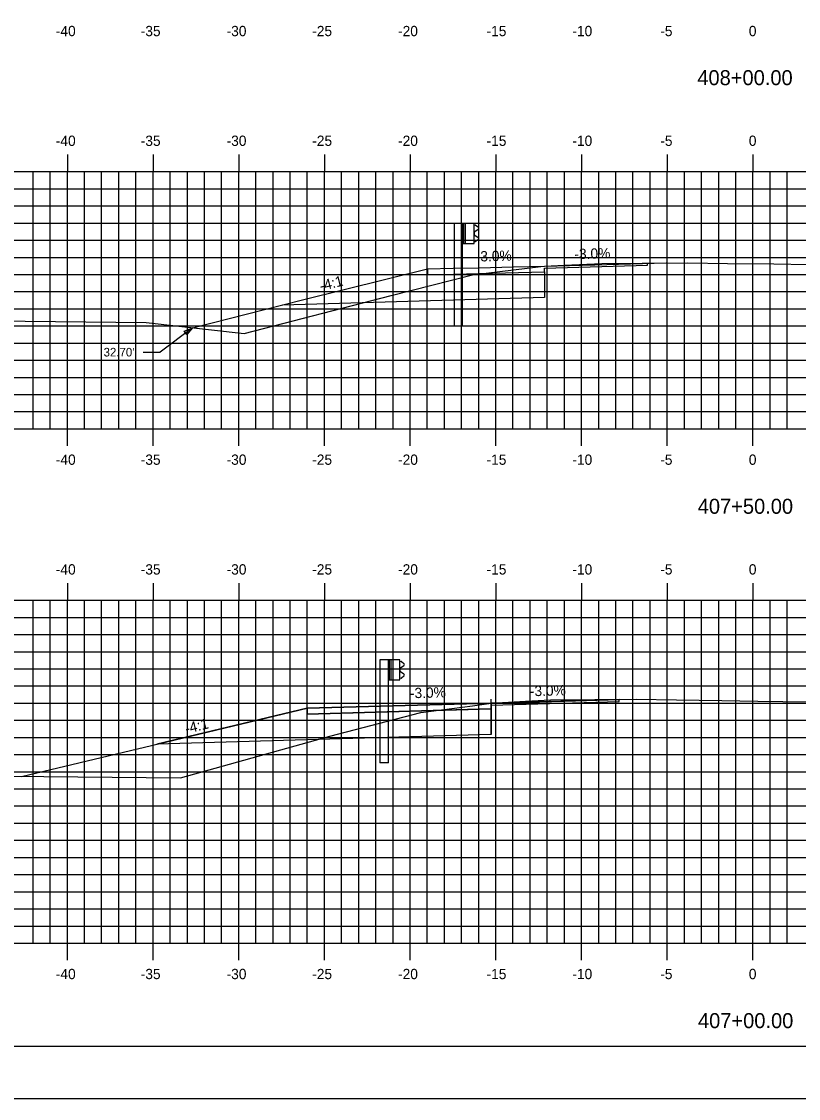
# Model space of a CAD drawing. Extents: x 1160718 to 1173142, y 616002 to 617630.
# Drawn here: x 1167258.6 to 1167304, y 616613.9 to 616676.7 of the extents above; entities that cross this region are included whole.
import ezdxf

# ---------------------------------------------------------------- set-up
doc = ezdxf.new("R2010")
doc.units = 0
for name, color, linetype in [('ANNOTATION', 7, 'Continuous'), ('BORDER', 7, 'Continuous'), ('D_Guardrail_Beam_Lt', 7, 'Continuous'), ('D_Roadway_Centerline', 7, 'Continuous'), ('D_Roadway_Edge_Shoulder', 7, 'Continuous'), ('D_Roadway_Edge_TW', 7, 'Continuous'), ('D_Roadway_SubGrade', 7, 'Continuous'), ('H_V ANNOTATION', 7, 'Continuous'), ('MAJOR', 7, 'Continuous'), ('MINOR', 7, 'Continuous'), ('PLOT BOUNDARY', 7, 'Continuous'), ('S_Roadway_Centerline', 7, 'Continuous'), ('SHADING', 7, 'Continuous')]:
    doc.layers.add(name, color=color, linetype=linetype)

msp = doc.modelspace()

# ---------------------------------------------------------------- linework, layer by layer
at = {"layer": 'ANNOTATION'}
for p, q in [((1167268.607, 616658.822), (1167266.736, 616657.397)), ((1167265.736, 616657.397), (1167266.736, 616657.397)), ((1167286.041, 616636.596), (1167286.041, 616635.096))]:
    msp.add_line(p, q, dxfattribs=at)
msp.add_lwpolyline([(1167268.133, 616658.618), (1167268.607, 616658.822), (1167268.285, 616658.419)], close=True, dxfattribs=at)
at = {"layer": 'BORDER'}
msp.add_line((1167226.316, 616616.928), (1167386.316, 616616.928), dxfattribs=at)
at = {"layer": 'D_Guardrail_Beam_Lt'}
for p, q in [((1167283.885, 616664.909), (1167283.885, 616658.909)), ((1167284.355, 616664.909), (1167283.885, 616664.909)), ((1167285.043, 616664.909), (1167284.355, 616664.909)), ((1167284.355, 616664.909), (1167284.355, 616663.742)), ((1167284.418, 616664.909), (1167284.418, 616663.742)), ((1167284.522, 616664.909), (1167284.522, 616663.742)), ((1167285.043, 616663.742), (1167285.043, 616664.909)), ((1167285.043, 616664.825), (1167285.117, 616664.811)), ((1167285.133, 616664.804), (1167285.276, 616664.704)), ((1167285.047, 616664.36), (1167285.047, 616664.29)), ((1167285.276, 616664.561), (1167285.081, 616664.425)), ((1167285.081, 616664.226), (1167285.276, 616664.09)), ((1167284.355, 616663.742), (1167285.043, 616663.742)), ((1167284.376, 616658.909), (1167284.376, 616663.742)), ((1167285.117, 616663.84), (1167285.043, 616663.825)), ((1167285.276, 616663.947), (1167285.133, 616663.847)), ((1167284.376, 616658.909), (1167283.885, 616658.909)), ((1167279.554, 616639.453), (1167279.554, 616633.453)), ((1167280.025, 616639.453), (1167279.554, 616639.453)), ((1167279.554, 616639.453), (1167279.554, 616633.453)), ((1167280.025, 616639.453), (1167279.554, 616639.453)), ((1167280.712, 616639.453), (1167280.025, 616639.453)), ((1167280.025, 616639.453), (1167280.025, 616638.286)), ((1167280.712, 616639.453), (1167280.025, 616639.453)), ((1167280.025, 616639.453), (1167280.025, 616638.286)), ((1167280.087, 616639.453), (1167280.087, 616638.286)), ((1167280.087, 616639.453), (1167280.087, 616638.286)), ((1167280.192, 616639.453), (1167280.192, 616638.286)), ((1167280.192, 616639.453), (1167280.192, 616638.286)), ((1167280.712, 616638.286), (1167280.712, 616639.453)), ((1167280.712, 616638.286), (1167280.712, 616639.453)), ((1167280.712, 616639.369), (1167280.787, 616639.355)), ((1167280.712, 616639.369), (1167280.787, 616639.355)), ((1167280.946, 616639.105), (1167280.751, 616638.969)), ((1167280.946, 616639.105), (1167280.751, 616638.969)), ((1167280.802, 616639.348), (1167280.946, 616639.248)), ((1167280.802, 616639.348), (1167280.946, 616639.248)), ((1167280.787, 616638.384), (1167280.712, 616638.369)), ((1167280.787, 616638.384), (1167280.712, 616638.369)), ((1167280.717, 616638.904), (1167280.717, 616638.834)), ((1167280.717, 616638.904), (1167280.717, 616638.834)), ((1167280.751, 616638.77), (1167280.946, 616638.634)), ((1167280.751, 616638.77), (1167280.946, 616638.634)), ((1167280.946, 616638.491), (1167280.802, 616638.391)), ((1167280.946, 616638.491), (1167280.802, 616638.391)), ((1167280.025, 616638.286), (1167280.712, 616638.286)), ((1167280.025, 616638.286), (1167280.712, 616638.286)), ((1167280.046, 616633.453), (1167280.046, 616638.286)), ((1167280.046, 616633.453), (1167280.046, 616638.286)), ((1167280.046, 616633.453), (1167279.554, 616633.453)), ((1167280.046, 616633.453), (1167279.554, 616633.453))]:
    msp.add_line(p, q, dxfattribs=at)
for centre, major_axis, start_param, end_param in [((1167285.109, 616664.77), (0.0417, 0), 0.959931, 1.376053), ((1167285.126, 616664.36), (-0.0789, 0), 5.323254, 6.283185), ((1167285.126, 616664.29), (-0.0789, 0), 6.283185, 7.243116), ((1167285.226, 616664.633), (0.0877, 0), 5.323254, 7.243116), ((1167285.109, 616663.881), (0.0417, 0), 4.907132, 5.323254), ((1167285.226, 616664.018), (0.0877, 0), 5.323254, 7.243116), ((1167280.796, 616638.904), (-0.0789, 0), 5.323254, 6.283185), ((1167280.796, 616638.904), (-0.0789, 0), 5.323254, 6.283185), ((1167280.779, 616639.314), (0.0417, 0), 0.959931, 1.376053), ((1167280.779, 616639.314), (0.0417, 0), 0.959931, 1.376053), ((1167280.896, 616639.177), (0.0877, 0), 5.323254, 7.243116), ((1167280.896, 616639.177), (0.0877, 0), 5.323254, 7.243116), ((1167280.796, 616638.834), (-0.0789, 0), 6.283185, 7.243116), ((1167280.796, 616638.834), (-0.0789, 0), 6.283185, 7.243116), ((1167280.779, 616638.425), (0.0417, 0), 4.907132, 5.323254), ((1167280.779, 616638.425), (0.0417, 0), 4.907132, 5.323254), ((1167280.896, 616638.562), (0.0877, 0), 5.323254, 7.243116), ((1167280.896, 616638.562), (0.0877, 0), 5.323254, 7.243116)]:
    msp.add_ellipse(centre, major_axis=major_axis, ratio=0.995501, start_param=start_param, end_param=end_param, dxfattribs=at)
at = {"layer": 'D_Roadway_Centerline'}
for points in [[(1167268.607, 616658.822), (1167275.034, 616660.443), (1167282.32, 616662.25), (1167283.818, 616662.288), (1167285.315, 616662.325), (1167287.337, 616662.376), (1167289.161, 616662.422), (1167292.087, 616662.495), (1167296.247, 616662.6)], [(1167258.641, 616632.654), (1167267.528, 616634.771), (1167275.315, 616636.625), (1167275.315, 616636.625), (1167275.315, 616636.625), (1167285.315, 616636.908), (1167285.56, 616636.915), (1167286.041, 616636.929), (1167290.971, 616637.07), (1167293.502, 616637.146)], [(1167258.641, 616632.654), (1167267.528, 616634.771), (1167275.315, 616636.625), (1167275.315, 616636.625), (1167275.315, 616636.625), (1167285.315, 616636.908), (1167285.56, 616636.915), (1167286.041, 616636.929), (1167290.971, 616637.07), (1167293.502, 616637.146)]]:
    msp.add_lwpolyline(points, dxfattribs=at)
at = {"layer": 'D_Roadway_Edge_Shoulder'}
msp.add_lwpolyline([(1167282.32, 616662.25), (1167282.32, 616661.917)], dxfattribs=at)
at = {"layer": 'D_Roadway_Edge_TW'}
for p, q in [((1167282.32, 616662.25), (1167282.32, 616661.917)), ((1167289.161, 616662.296), (1167295.161, 616662.468)), ((1167289.161, 616662.087), (1167289.161, 616662.296)), ((1167295.161, 616662.468), (1167295.161, 616662.593)), ((1167282.32, 616661.917), (1167289.161, 616662.087))]:
    msp.add_line(p, q, dxfattribs=at)
msp.add_lwpolyline([(1167293.502, 616637.146), (1167286.041, 616636.929), (1167285.315, 616636.908), (1167275.315, 616636.625), (1167275.315, 616636.292), (1167286.041, 616636.596), (1167286.041, 616636.804), (1167293.502, 616637.021)], close=True, dxfattribs=at)
for points in [[(1167293.502, 616637.146), (1167286.041, 616636.929), (1167286.039, 616636.929), (1167286.041, 616636.804), (1167293.502, 616637.021), (1167293.502, 616637.146)], [(1167293.502, 616637.146), (1167286.041, 616636.929), (1167286.041, 616636.929), (1167286.041, 616636.804), (1167293.502, 616637.021), (1167293.502, 616637.146)]]:
    msp.add_lwpolyline(points, dxfattribs=at)
at = {"layer": 'D_Roadway_SubGrade'}
for p, q in [((1167286.041, 616636.929), (1167286.041, 616636.596)), ((1167286.041, 616636.596), (1167286.041, 616635.096)), ((1167286.041, 616635.096), (1167266.534, 616634.534))]:
    msp.add_line(p, q, dxfattribs=at)
msp.add_lwpolyline([(1167286.041, 616635.096), (1167286.041, 616635.304), (1167286.041, 616636.596), (1167285.315, 616636.575), (1167275.315, 616636.292), (1167275.315, 616636.625), (1167266.534, 616634.534)], dxfattribs=at)
at = {"layer": 'MAJOR'}
for p, q in [((1167261.315, 616668.93), (1167261.315, 616667.928)), ((1167266.315, 616668.93), (1167266.315, 616667.928)), ((1167271.315, 616668.93), (1167271.315, 616667.928)), ((1167276.315, 616668.93), (1167276.315, 616667.928)), ((1167281.315, 616668.93), (1167281.315, 616667.928)), ((1167286.315, 616668.93), (1167286.315, 616667.928)), ((1167291.315, 616668.93), (1167291.315, 616667.928)), ((1167296.315, 616668.93), (1167296.315, 616667.928)), ((1167301.315, 616668.93), (1167301.315, 616667.928)), ((1167231.315, 616667.928), (1167371.315, 616667.928)), ((1167231.315, 616667.928), (1167371.315, 616667.928)), ((1167261.315, 616652.928), (1167261.315, 616667.928)), ((1167266.315, 616652.928), (1167266.315, 616667.928)), ((1167271.315, 616652.928), (1167271.315, 616667.928)), ((1167276.315, 616652.928), (1167276.315, 616667.928)), ((1167281.315, 616652.928), (1167281.315, 616667.928)), ((1167286.315, 616652.928), (1167286.315, 616667.928)), ((1167291.315, 616652.928), (1167291.315, 616667.928)), ((1167296.315, 616652.928), (1167296.315, 616667.928)), ((1167301.315, 616652.928), (1167301.315, 616667.928)), ((1167231.315, 616662.928), (1167371.315, 616662.928)), ((1167231.315, 616657.928), (1167371.315, 616657.928)), ((1167231.315, 616652.928), (1167371.315, 616652.928)), ((1167231.315, 616652.928), (1167371.315, 616652.928)), ((1167261.315, 616651.926), (1167261.315, 616652.928)), ((1167266.315, 616651.926), (1167266.315, 616652.928)), ((1167271.315, 616651.926), (1167271.315, 616652.928)), ((1167276.315, 616651.926), (1167276.315, 616652.928)), ((1167281.315, 616651.926), (1167281.315, 616652.928)), ((1167286.315, 616651.926), (1167286.315, 616652.928)), ((1167291.315, 616651.926), (1167291.315, 616652.928)), ((1167296.315, 616651.926), (1167296.315, 616652.928)), ((1167301.315, 616651.926), (1167301.315, 616652.928)), ((1167261.315, 616643.93), (1167261.315, 616642.928)), ((1167266.315, 616643.93), (1167266.315, 616642.928)), ((1167271.315, 616643.93), (1167271.315, 616642.928)), ((1167276.315, 616643.93), (1167276.315, 616642.928)), ((1167281.315, 616643.93), (1167281.315, 616642.928)), ((1167286.315, 616643.93), (1167286.315, 616642.928)), ((1167291.315, 616643.93), (1167291.315, 616642.928)), ((1167296.315, 616643.93), (1167296.315, 616642.928)), ((1167301.315, 616643.93), (1167301.315, 616642.928)), ((1167231.315, 616642.928), (1167371.315, 616642.928)), ((1167231.315, 616642.928), (1167371.315, 616642.928)), ((1167261.315, 616622.928), (1167261.315, 616642.928)), ((1167266.315, 616622.928), (1167266.315, 616642.928)), ((1167271.315, 616622.928), (1167271.315, 616642.928)), ((1167276.315, 616622.928), (1167276.315, 616642.928)), ((1167281.315, 616622.928), (1167281.315, 616642.928)), ((1167286.315, 616622.928), (1167286.315, 616642.928)), ((1167291.315, 616622.928), (1167291.315, 616642.928)), ((1167296.315, 616622.928), (1167296.315, 616642.928)), ((1167301.315, 616622.928), (1167301.315, 616642.928)), ((1167231.315, 616637.928), (1167371.315, 616637.928)), ((1167231.315, 616632.928), (1167371.315, 616632.928)), ((1167231.315, 616627.928), (1167371.315, 616627.928)), ((1167231.315, 616622.928), (1167371.315, 616622.928)), ((1167231.315, 616622.928), (1167371.315, 616622.928)), ((1167261.315, 616621.926), (1167261.315, 616622.928)), ((1167266.315, 616621.926), (1167266.315, 616622.928)), ((1167271.315, 616621.926), (1167271.315, 616622.928)), ((1167276.315, 616621.926), (1167276.315, 616622.928)), ((1167281.315, 616621.926), (1167281.315, 616622.928)), ((1167286.315, 616621.926), (1167286.315, 616622.928)), ((1167291.315, 616621.926), (1167291.315, 616622.928)), ((1167296.315, 616621.926), (1167296.315, 616622.928)), ((1167301.315, 616621.926), (1167301.315, 616622.928))]:
    msp.add_line(p, q, dxfattribs=at)
at = {"layer": 'MINOR'}
for p, q in [((1167259.315, 616652.928), (1167259.315, 616667.928)), ((1167260.315, 616652.928), (1167260.315, 616667.928)), ((1167262.315, 616652.928), (1167262.315, 616667.928)), ((1167263.315, 616652.928), (1167263.315, 616667.928)), ((1167264.315, 616652.928), (1167264.315, 616667.928)), ((1167265.315, 616652.928), (1167265.315, 616667.928)), ((1167267.315, 616652.928), (1167267.315, 616667.928)), ((1167268.315, 616652.928), (1167268.315, 616667.928)), ((1167269.315, 616652.928), (1167269.315, 616667.928)), ((1167270.315, 616652.928), (1167270.315, 616667.928)), ((1167272.315, 616652.928), (1167272.315, 616667.928)), ((1167273.315, 616652.928), (1167273.315, 616667.928)), ((1167274.315, 616652.928), (1167274.315, 616667.928)), ((1167275.315, 616652.928), (1167275.315, 616667.928)), ((1167277.315, 616652.928), (1167277.315, 616667.928)), ((1167278.315, 616652.928), (1167278.315, 616667.928)), ((1167279.315, 616652.928), (1167279.315, 616667.928)), ((1167280.315, 616652.928), (1167280.315, 616667.928)), ((1167282.315, 616652.928), (1167282.315, 616667.928)), ((1167283.315, 616652.928), (1167283.315, 616667.928)), ((1167284.315, 616652.928), (1167284.315, 616667.928)), ((1167285.315, 616652.928), (1167285.315, 616667.928)), ((1167287.315, 616652.928), (1167287.315, 616667.928)), ((1167288.315, 616652.928), (1167288.315, 616667.928)), ((1167289.315, 616652.928), (1167289.315, 616667.928)), ((1167290.315, 616652.928), (1167290.315, 616667.928)), ((1167292.315, 616652.928), (1167292.315, 616667.928)), ((1167293.315, 616652.928), (1167293.315, 616667.928)), ((1167294.315, 616652.928), (1167294.315, 616667.928)), ((1167295.315, 616652.928), (1167295.315, 616667.928)), ((1167297.315, 616652.928), (1167297.315, 616667.928)), ((1167298.315, 616652.928), (1167298.315, 616667.928)), ((1167299.315, 616652.928), (1167299.315, 616667.928)), ((1167300.315, 616652.928), (1167300.315, 616667.928)), ((1167302.315, 616652.928), (1167302.315, 616667.928)), ((1167303.315, 616652.928), (1167303.315, 616667.928)), ((1167231.315, 616666.928), (1167371.315, 616666.928)), ((1167231.315, 616665.928), (1167371.315, 616665.928)), ((1167231.315, 616664.928), (1167371.315, 616664.928)), ((1167231.315, 616663.928), (1167371.315, 616663.928)), ((1167231.315, 616661.928), (1167371.315, 616661.928)), ((1167231.315, 616660.928), (1167371.315, 616660.928)), ((1167231.315, 616659.928), (1167371.315, 616659.928)), ((1167231.315, 616658.928), (1167371.315, 616658.928)), ((1167231.315, 616656.928), (1167371.315, 616656.928)), ((1167231.315, 616655.928), (1167371.315, 616655.928)), ((1167231.315, 616654.928), (1167371.315, 616654.928)), ((1167231.315, 616653.928), (1167371.315, 616653.928)), ((1167259.315, 616622.928), (1167259.315, 616642.928)), ((1167260.315, 616622.928), (1167260.315, 616642.928)), ((1167262.315, 616622.928), (1167262.315, 616642.928)), ((1167263.315, 616622.928), (1167263.315, 616642.928)), ((1167264.315, 616622.928), (1167264.315, 616642.928)), ((1167265.315, 616622.928), (1167265.315, 616642.928)), ((1167267.315, 616622.928), (1167267.315, 616642.928)), ((1167268.315, 616622.928), (1167268.315, 616642.928)), ((1167269.315, 616622.928), (1167269.315, 616642.928)), ((1167270.315, 616622.928), (1167270.315, 616642.928)), ((1167272.315, 616622.928), (1167272.315, 616642.928)), ((1167273.315, 616622.928), (1167273.315, 616642.928)), ((1167274.315, 616622.928), (1167274.315, 616642.928)), ((1167275.315, 616622.928), (1167275.315, 616642.928)), ((1167277.315, 616622.928), (1167277.315, 616642.928)), ((1167278.315, 616622.928), (1167278.315, 616642.928)), ((1167279.315, 616622.928), (1167279.315, 616642.928)), ((1167280.315, 616622.928), (1167280.315, 616642.928)), ((1167282.315, 616622.928), (1167282.315, 616642.928)), ((1167283.315, 616622.928), (1167283.315, 616642.928)), ((1167284.315, 616622.928), (1167284.315, 616642.928)), ((1167285.315, 616622.928), (1167285.315, 616642.928)), ((1167287.315, 616622.928), (1167287.315, 616642.928)), ((1167288.315, 616622.928), (1167288.315, 616642.928)), ((1167289.315, 616622.928), (1167289.315, 616642.928)), ((1167290.315, 616622.928), (1167290.315, 616642.928)), ((1167292.315, 616622.928), (1167292.315, 616642.928)), ((1167293.315, 616622.928), (1167293.315, 616642.928)), ((1167294.315, 616622.928), (1167294.315, 616642.928)), ((1167295.315, 616622.928), (1167295.315, 616642.928)), ((1167297.315, 616622.928), (1167297.315, 616642.928)), ((1167298.315, 616622.928), (1167298.315, 616642.928)), ((1167299.315, 616622.928), (1167299.315, 616642.928)), ((1167300.315, 616622.928), (1167300.315, 616642.928)), ((1167302.315, 616622.928), (1167302.315, 616642.928)), ((1167303.315, 616622.928), (1167303.315, 616642.928)), ((1167231.315, 616641.928), (1167371.315, 616641.928)), ((1167231.315, 616640.928), (1167371.315, 616640.928)), ((1167231.315, 616639.928), (1167371.315, 616639.928)), ((1167231.315, 616638.928), (1167371.315, 616638.928)), ((1167231.315, 616636.928), (1167371.315, 616636.928)), ((1167231.315, 616635.928), (1167371.315, 616635.928)), ((1167231.315, 616634.928), (1167371.315, 616634.928)), ((1167231.315, 616633.928), (1167371.315, 616633.928)), ((1167231.315, 616631.928), (1167371.315, 616631.928)), ((1167231.315, 616630.928), (1167371.315, 616630.928)), ((1167231.315, 616629.928), (1167371.315, 616629.928)), ((1167231.315, 616628.928), (1167371.315, 616628.928)), ((1167231.315, 616626.928), (1167371.315, 616626.928)), ((1167231.315, 616625.928), (1167371.315, 616625.928)), ((1167231.315, 616624.928), (1167371.315, 616624.928)), ((1167231.315, 616623.928), (1167371.315, 616623.928))]:
    msp.add_line(p, q, dxfattribs=at)
at = {"layer": 'PLOT BOUNDARY'}
msp.add_line((1167286.041, 616636.804), (1167286.041, 616637.157), dxfattribs=at)
msp.add_lwpolyline([(1167218.222, 616613.869), (1167388.222, 616613.869), (1167388.222, 616723.869), (1167218.222, 616723.869)], close=True, dxfattribs=at)
at = {"layer": 'S_Roadway_Centerline'}
for points in [[(1167231.315, 616659.326), (1167237.494, 616659.195), (1167246.501, 616659.338), (1167265.905, 616659.119), (1167271.637, 616658.489), (1167280.204, 616660.695), (1167284.944, 616661.905), (1167288.935, 616662.39), (1167289.161, 616662.421), (1167290.325, 616662.475), (1167292.505, 616662.578), (1167294.855, 616662.591), (1167297.516, 616662.607), (1167299.838, 616662.576), (1167302.528, 616662.541), (1167304.53, 616662.503)], [(1167231.315, 616632.791), (1167233.532, 616632.735), (1167247.04, 616632.784), (1167257.944, 616632.661), (1167267.919, 616632.564), (1167276.623, 616635.005), (1167281.944, 616636.38), (1167284.961, 616636.765), (1167286.041, 616636.929), (1167288.054, 616637.043), (1167289.495, 616637.12), (1167292.091, 616637.136), (1167294.502, 616637.154), (1167296.849, 616637.122), (1167299.509, 616637.085), (1167301.607, 616637.05), (1167304.516, 616636.999)]]:
    msp.add_lwpolyline(points, dxfattribs=at)
at = {"layer": 'SHADING'}
for p, q in [((1167289.161, 616662.087), (1167289.161, 616660.587)), ((1167289.161, 616660.587), (1167273.863, 616660.147))]:
    msp.add_line(p, q, dxfattribs=at)

# ---------------------------------------------------------------- texts
at = {"layer": 'ANNOTATION'}
for s, rotation, p in [('-3.0%', 1.6455, (1167290.907, 616662.817)), ('-3.0%', 1.6455, (1167285.151, 616662.678)), ('-4:1', 14.03624, (1167276.106, 616660.954)), ('-3.0%', 1.73872, (1167281.31, 616637.207)), ('-3.0%', 1.73872, (1167288.31, 616637.325)), ('-3.0%', 1.73872, (1167288.31, 616637.325)), ('-4:1', 14.03624, (1167268.258, 616635.134)), ('-4:1', 14.03624, (1167268.258, 616635.134))]:
    msp.add_text(s, height=0.6, rotation=rotation, dxfattribs=at).set_placement(p)
msp.add_text("32.70'", height=0.5, dxfattribs=at).set_placement((1167263.427, 616657.147))
at = {"layer": 'H_V ANNOTATION'}
for s, height, p in [('-40', 0.6, (1167260.641, 616675.828)), ('-35', 0.6, (1167265.596, 616675.828)), ('-30', 0.6, (1167270.604, 616675.828)), ('-25', 0.6, (1167275.601, 616675.828)), ('-20', 0.6, (1167280.609, 616675.828)), ('-15', 0.6, (1167285.772, 616675.828)), ('-10', 0.6, (1167290.78, 616675.828)), ('-5', 0.6, (1167295.906, 616675.828)), ('0', 0.6, (1167301.074, 616675.828)), ('408+00.00', 0.875, (1167298.069, 616672.971)), ('-40', 0.6, (1167260.641, 616669.428)), ('-35', 0.6, (1167265.596, 616669.428)), ('-30', 0.6, (1167270.604, 616669.428)), ('-25', 0.6, (1167275.601, 616669.428)), ('-20', 0.6, (1167280.609, 616669.428)), ('-15', 0.6, (1167285.772, 616669.428)), ('-10', 0.6, (1167290.78, 616669.428)), ('-5', 0.6, (1167295.906, 616669.428)), ('0', 0.6, (1167301.074, 616669.428)), ('-40', 0.6, (1167260.641, 616650.828)), ('-35', 0.6, (1167265.596, 616650.828)), ('-30', 0.6, (1167270.604, 616650.828)), ('-25', 0.6, (1167275.601, 616650.828)), ('-20', 0.6, (1167280.609, 616650.828)), ('-15', 0.6, (1167285.772, 616650.828)), ('-10', 0.6, (1167290.78, 616650.828)), ('-5', 0.6, (1167295.906, 616650.828)), ('0', 0.6, (1167301.074, 616650.828)), ('407+50.00', 0.875, (1167298.093, 616647.971)), ('-40', 0.6, (1167260.641, 616644.428)), ('-35', 0.6, (1167265.596, 616644.428)), ('-30', 0.6, (1167270.604, 616644.428)), ('-25', 0.6, (1167275.601, 616644.428)), ('-20', 0.6, (1167280.609, 616644.428)), ('-15', 0.6, (1167285.772, 616644.428)), ('-10', 0.6, (1167290.78, 616644.428)), ('-5', 0.6, (1167295.906, 616644.428)), ('0', 0.6, (1167301.074, 616644.428)), ('-40', 0.6, (1167260.641, 616620.828)), ('-35', 0.6, (1167265.596, 616620.828)), ('-30', 0.6, (1167270.604, 616620.828)), ('-25', 0.6, (1167275.601, 616620.828)), ('-20', 0.6, (1167280.609, 616620.828)), ('-15', 0.6, (1167285.772, 616620.828)), ('-10', 0.6, (1167290.78, 616620.828)), ('-5', 0.6, (1167295.906, 616620.828)), ('0', 0.6, (1167301.074, 616620.828)), ('407+00.00', 0.875, (1167298.108, 616617.971))]:
    msp.add_text(s, height=height, dxfattribs=at).set_placement(p)

doc.saveas('drawing.dxf')
